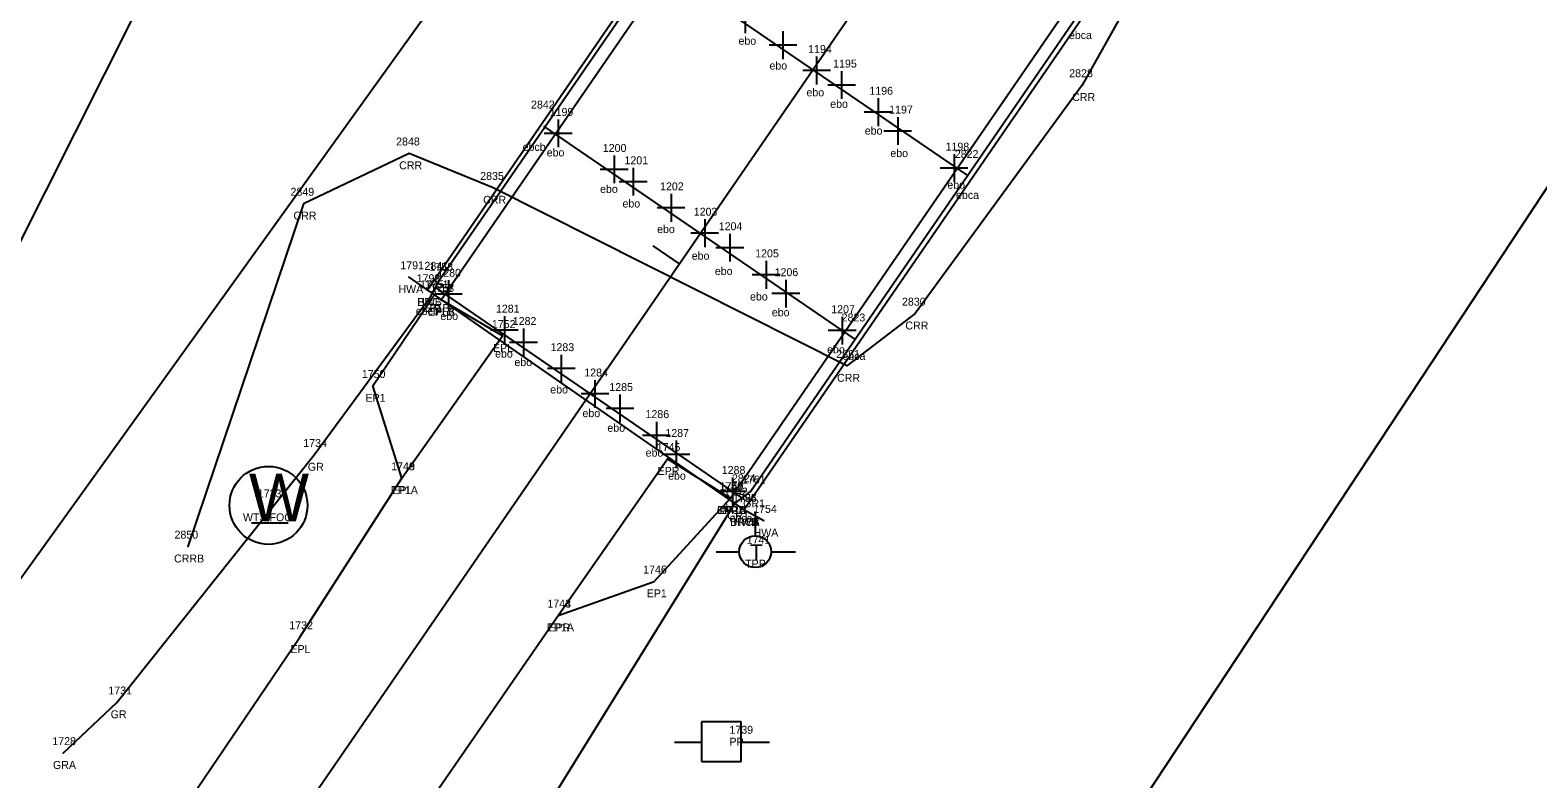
# Model space of a CAD drawing. Extents: x 2266664 to 2272542, y 716533 to 724777.
# Drawn here: x 2268915.8 to 2269105.7, y 719810.9 to 719905.2 of the extents above; entities that cross this region are included whole.
import ezdxf

# ---------------------------------------------------------------- set-up
doc = ezdxf.new("R2010")
doc.units = 0
for name, color, linetype in [('RD_EX_Bridge', 7, 'Continuous'), ('RD_EX_Bridge_txCode', 7, 'Continuous'), ('RD_EX_Conc', 7, 'Continuous'), ('RD_EX_Conc_txCode', 7, 'Continuous'), ('RD_EX_GuardRail', 7, 'Continuous'), ('RD_EX_GuardRail_txCode', 7, 'Continuous'), ('RD_EX_H2O', 7, 'Continuous'), ('RD_EX_H2O_txCode', 7, 'Continuous'), ('RD_EX_Misc', 7, 'Continuous'), ('RD_EX_Misc_txCode', 7, 'Continuous'), ('RD_EX_Road', 7, 'Continuous'), ('RD_EX_Road_txCode', 7, 'Continuous'), ('RD_EX_UT', 7, 'Continuous'), ('RD_EX_UT_txCode', 7, 'Continuous'), ('RD_EX_VEG', 7, 'Continuous'), ('RD_HC_Cl', 7, 'Continuous'), ('RD_HC_Data_Tic', 7, 'Continuous'), ('RD_SMD_Locator', 7, 'Continuous')]:
    doc.layers.add(name, color=color, linetype=linetype)

msp = doc.modelspace()

# ---------------------------------------------------------------- linework, layer by layer
at = {"layer": 'RD_EX_Bridge'}
for p, q in [((2268963.52, 719874.06), (2268965.85, 719872.44)), ((2269008.24, 719843.39), (2269005.71, 719844.75))]:
    msp.add_line(p, q, dxfattribs=at)
msp.add_lwpolyline([(2269005.71, 719844.75), (2269233.07, 720175.43), (2269193.18, 720202.86), (2268965.85, 719872.44), (2269005.71, 719844.75)], dxfattribs=at)
at = {"layer": 'RD_EX_Conc'}
for points in [[(2268967.59, 719871.21), (2269010.36, 719933.37), (2269052.74, 719994.95), (2269096, 720057.76), (2269138.05, 720118.85), (2269194.93, 720201.62)], [(2269004.04, 719846.24), (2269046.75, 719908.42), (2269089.1, 719970.17), (2269131.56, 720031.81), (2269174.47, 720094.11), (2269231.14, 720176.62)]]:
    msp.add_lwpolyline(points, dxfattribs=at)
at = {"layer": 'RD_EX_GuardRail'}
for points in [[(2268966.72, 719781.34), (2268981.11, 719807.65), (2269004.56, 719845.55), (2269006.56, 719847.08), (2269048.04, 719907.43), (2269090.37, 719969.18), (2269132.94, 720030.91), (2269175.81, 720093.43), (2269231.32, 720174.06), (2269253.93, 720204.36), (2269271.7, 720223.93)], [(2268919.97, 719814.14), (2268926.75, 719820.52), (2268951.58, 719851.69), (2268966.29, 719871.68), (2268967.47, 719873.87), (2269009.19, 719934.42), (2269051.44, 719995.68), (2269094.56, 720058.42), (2269136.79, 720119.9), (2269193.57, 720202.38)]]:
    msp.add_lwpolyline(points, dxfattribs=at)
at = {"layer": 'RD_EX_H2O'}
for points in [[(2269026.84, 720028.11), (2268972.74, 719968.59), (2268939.93, 719929), (2268910.32, 719870.19), (2268897.54, 719838.49), (2268888.45, 719839.47), (2268875.86, 719855.03)], [(2269107.58, 719973.56), (2269095.28, 719977.57), (2269070.98, 719938.72), (2269048.32, 719898.25), (2269027.3, 719869.48), (2269018.7, 719862.89), (2268974.14, 719885.31), (2268963.55, 719889.65), (2268950.25, 719883.32), (2268935.68, 719840.14)]]:
    msp.add_lwpolyline(points, dxfattribs=at)
at = {"layer": 'RD_EX_Misc'}
for p, q in [((2269033.91, 719886.87), (2268994.62, 719913.71)), ((2269005.87, 719908.31), (2269005.87, 719904.81)), ((2269010.63, 719905.03), (2269010.63, 719901.53)), ((2269012.38, 719903.28), (2269008.88, 719903.28)), ((2269014.87, 719901.84), (2269014.87, 719898.34)), ((2269016.62, 719900.09), (2269013.12, 719900.09)), ((2269018.02, 719900.01), (2269018.02, 719896.51)), ((2269019.77, 719898.26), (2269016.27, 719898.26)), ((2269022.61, 719896.59), (2269022.61, 719893.09)), ((2269024.36, 719894.84), (2269020.86, 719894.84)), ((2269019.66, 719866.29), (2268980.54, 719893.1)), ((2268982.32, 719893.92), (2268982.32, 719890.42)), ((2269025.09, 719894.22), (2269025.09, 719890.72)), ((2268984.07, 719892.17), (2268980.57, 719892.17)), ((2269026.84, 719892.47), (2269023.34, 719892.47)), ((2268989.38, 719889.39), (2268989.38, 719885.89)), ((2269032.19, 719889.56), (2269032.19, 719886.06)), ((2268991.13, 719887.64), (2268987.63, 719887.64)), ((2268991.78, 719887.83), (2268991.78, 719884.33)), ((2269033.94, 719887.81), (2269030.44, 719887.81)), ((2268993.53, 719886.08), (2268990.03, 719886.08)), ((2268996.54, 719884.55), (2268996.54, 719881.05)), ((2268998.29, 719882.8), (2268994.79, 719882.8)), ((2269000.79, 719881.36), (2269000.79, 719877.86)), ((2269002.54, 719879.61), (2268999.04, 719879.61)), ((2269003.94, 719879.53), (2269003.94, 719876.03)), ((2269005.69, 719877.78), (2269002.19, 719877.78)), ((2269008.52, 719876.11), (2269008.52, 719872.61)), ((2268968.5, 719873.67), (2268968.5, 719870.17)), ((2269010.27, 719874.36), (2269006.77, 719874.36)), ((2269011, 719873.74), (2269011, 719870.24)), ((2268970.25, 719871.92), (2268966.75, 719871.92)), ((2269005.84, 719846.04), (2268966.84, 719872.79)), ((2269012.75, 719871.99), (2269009.25, 719871.99)), ((2268975.55, 719869.15), (2268975.55, 719865.65)), ((2269018.1, 719869.08), (2269018.1, 719865.58)), ((2268977.3, 719867.4), (2268973.8, 719867.4)), ((2268977.96, 719867.59), (2268977.96, 719864.09)), ((2269019.85, 719867.33), (2269016.35, 719867.33)), ((2268979.71, 719865.84), (2268976.21, 719865.84)), ((2268982.72, 719864.3), (2268982.72, 719860.8)), ((2268984.47, 719862.55), (2268980.97, 719862.55)), ((2268986.96, 719861.11), (2268986.96, 719857.61)), ((2268988.71, 719859.36), (2268985.21, 719859.36)), ((2268990.11, 719859.28), (2268990.11, 719855.78)), ((2268991.86, 719857.53), (2268988.36, 719857.53)), ((2268994.7, 719855.87), (2268994.7, 719852.37)), ((2268996.45, 719854.12), (2268992.95, 719854.12)), ((2268997.18, 719853.5), (2268997.18, 719850)), ((2268998.93, 719851.75), (2268995.43, 719851.75)), ((2269006.03, 719847.08), (2269002.53, 719847.08)), ((2269004.28, 719848.83), (2269004.28, 719845.33))]:
    msp.add_line(p, q, dxfattribs=at)
at = {"layer": 'RD_EX_Road'}
for points in [[(2268844.96, 719677.11), (2268896.55, 719753.72), (2268929.83, 719802.76), (2268931.8, 719802.17), (2268949.81, 719828.73), (2268962.65, 719848.75), (2268975.33, 719866.66), (2268967.59, 719871.21)], [(2268962.65, 719848.75), (2268958.99, 719860.37), (2268966.63, 719871.67)], [(2268842.45, 719629.17), (2268908.71, 719725.27), (2268929.59, 719755.12), (2268982.31, 719831.46), (2268996.08, 719851.17), (2269004.04, 719846.24)], [(2268982.31, 719831.46), (2268994.4, 719835.75), (2269004.04, 719846.24)]]:
    msp.add_lwpolyline(points, dxfattribs=at)
at = {"layer": 'RD_EX_UT'}
for p, q in [((2269007.14, 719844.56), (2269007.14, 719841.49)), ((2268943.72, 719843.13), (2268948.34, 719843.13)), ((2269002.21, 719839.5), (2269005.14, 719839.5)), ((2269009.14, 719839.5), (2269012.21, 719839.5)), ((2269005.39, 719818.08), (2269000.39, 719818.08)), ((2269000.39, 719818.08), (2269000.39, 719813.08)), ((2269005.39, 719813.08), (2269005.39, 719818.08)), ((2268996.96, 719815.51), (2269000.43, 719815.51)), ((2269005.32, 719815.51), (2269008.96, 719815.51)), ((2269000.39, 719813.08), (2269005.39, 719813.08))]:
    msp.add_line(p, q, dxfattribs=at)
for centre, radius in [((2268945.84, 719845.33), 4.91), ((2269007.14, 719839.49), 2)]:
    msp.add_circle(centre, radius, dxfattribs=at)
at = {"layer": 'RD_EX_VEG'}
for points in [[(2268819.78, 719716.8), (2268871.54, 719776.21), (2269193.85, 720224.65), (2269408.57, 720538.5), (2269589.67, 720791.77), (2270047.56, 721479.8), (2270363.13, 721951.09), (2270746.65, 722498.38), (2270919.94, 722752.82), (2271017.26, 722923.37)], [(2268988.31, 719705.64), (2269316.7, 720203.55), (2269323.19, 720195.95)]]:
    msp.add_lwpolyline(points, dxfattribs=at)
at = {"layer": 'RD_HC_Cl'}
msp.add_line((2267342.91, 717471.2), (2272360.46, 724762.59), dxfattribs=at)
at = {"layer": 'RD_HC_Data_Tic'}
msp.add_line((2268997.6, 719875.76), (2268994.31, 719878.03), dxfattribs=at)
at = {"layer": 'RD_SMD_Locator'}
for centre in [(2269048.32, 719898.25), (2268963.55, 719889.65), (2268974.14, 719885.31), (2268950.25, 719883.32), (2268963.52, 719874.06), (2268967.47, 719873.87), (2268965.85, 719872.44), (2268965.85, 719872.44), (2268966.29, 719871.68), (2268966.63, 719871.67), (2268967.59, 719871.21), (2268967.59, 719871.21), (2269027.3, 719869.48), (2268975.33, 719866.66), (2269018.7, 719862.89), (2268958.99, 719860.37), (2268951.58, 719851.69), (2268996.08, 719851.17), (2268962.65, 719848.75), (2268962.65, 719848.75), (2269006.56, 719847.08), (2269004.04, 719846.24), (2269004.04, 719846.24), (2269004.04, 719846.24), (2269004.56, 719845.55), (2269005.71, 719844.75), (2269005.71, 719844.75), (2269005.71, 719844.75), (2269008.24, 719843.39), (2268935.68, 719840.14), (2268994.4, 719835.75), (2268982.31, 719831.46), (2268982.31, 719831.46), (2268949.81, 719828.73), (2268926.75, 719820.52), (2268919.97, 719814.14)]:
    msp.add_circle(centre, 0.001, dxfattribs=at)

# ---------------------------------------------------------------- texts
at = {"layer": 'RD_EX_Bridge_txCode'}
for s, p in [('1791', (2268962.45, 719875.06)), ('1792', (2268964.51, 719873.44)), ('1793', (2268964.51, 719873.44)), ('HWA', (2268962.21, 719872.06)), ('HWB', (2268964.56, 719870.44)), ('BRC', (2268964.6, 719870.44)), ('1756', (2269004.34, 719845.75)), ('1794', (2269004.36, 719845.75)), ('1755', (2269004.36, 719845.75)), ('1754', (2269006.89, 719844.39)), ('BRCA', (2269003.97, 719842.75)), ('BRCB', (2269003.98, 719842.75)), ('HWB', (2269004.42, 719842.75)), ('HWA', (2269006.93, 719841.39))]:
    msp.add_text(s, height=1, dxfattribs=at).set_placement(p)
at = {"layer": 'RD_EX_Conc_txCode'}
for s, p in [('1757', (2268966.24, 719872.21)), ('CFLA', (2268965.89, 719869.21)), ('1759', (2269002.69, 719847.24)), ('CFRA', (2269002.32, 719844.24))]:
    msp.add_text(s, height=1, dxfattribs=at).set_placement(p)
at = {"layer": 'RD_EX_GuardRail_txCode'}
for s, p in [('1758', (2268966.12, 719874.87)), ('1735', (2268964.94, 719872.68)), ('GR', (2268966.69, 719871.87)), ('GR', (2268965.51, 719869.68)), ('1734', (2268950.23, 719852.69)), ('GR', (2268950.8, 719849.69)), ('1761', (2269005.48, 719848.08)), ('1742', (2269003.22, 719846.55)), ('GR1', (2269005.62, 719845.08)), ('GR1', (2269003.62, 719843.55)), ('1731', (2268925.68, 719821.52)), ('GR', (2268925.97, 719818.52)), ('1728', (2268918.62, 719815.14)), ('GRA', (2268918.7, 719812.14))]:
    msp.add_text(s, height=1, dxfattribs=at).set_placement(p)
at = {"layer": 'RD_EX_H2O_txCode'}
for s, p in [('2828', (2269046.69, 719899.25)), ('CRR', (2269047.06, 719896.25)), ('2848', (2268961.92, 719890.65)), ('CRR', (2268962.3, 719887.65)), ('2835', (2268972.51, 719886.31)), ('2849', (2268948.62, 719884.32)), ('CRR', (2268972.88, 719883.31)), ('CRR', (2268948.99, 719881.32)), ('2830', (2269025.63, 719870.48)), ('CRR', (2269026.05, 719867.48)), ('2831', (2269017.35, 719863.89)), ('CRR', (2269017.45, 719860.89)), ('2850', (2268934.01, 719841.14)), ('CRRB', (2268933.95, 719838.14))]:
    msp.add_text(s, height=1, dxfattribs=at).set_placement(p)
at = {"layer": 'RD_EX_Misc_txCode'}
for s, p in [('ebo', (2269005.04, 719903.34)), ('ebca', (2269046.65, 719904.05)), ('1194', (2269013.81, 719902.29)), ('ebo', (2269008.94, 719900.21)), ('1195', (2269016.96, 719900.46)), ('ebo', (2269013.6, 719896.84)), ('ebo', (2269016.59, 719895.39)), ('1196', (2269021.52, 719897.04)), ('2842', (2268978.91, 719895.3)), ('1199', (2268981.26, 719894.37)), ('1197', (2269024.02, 719894.67)), ('ebo', (2269020.94, 719892.02)), ('ebcb', (2268977.85, 719889.97)), ('1200', (2268987.95, 719889.84)), ('1198', (2269031.12, 719890.01)), ('ebo', (2268980.88, 719889.27)), ('1201', (2268990.68, 719888.28)), ('ebo', (2269024.16, 719889.19)), ('2822', (2269032.28, 719889.07)), ('ebo', (2268987.6, 719884.67)), ('1202', (2268995.16, 719885)), ('ebo', (2269031.34, 719885.21)), ('ebo', (2268990.43, 719882.84)), ('ebca', (2269032.43, 719883.92)), ('1203', (2268999.4, 719881.81)), ('ebo', (2268994.79, 719879.62)), ('1204', (2269002.55, 719879.98)), ('1205', (2269007.14, 719876.56)), ('2841', (2268965.49, 719874.99)), ('ebo', (2268999.15, 719876.26)), ('1280', (2268967.11, 719874.12)), ('ebo', (2269002.06, 719874.34)), ('1206', (2269009.59, 719874.19)), ('ebo', (2269006.49, 719871.13)), ('ebcb', (2268964.39, 719869.31)), ('1281', (2268974.49, 719869.6)), ('ebo', (2269009.24, 719869.14)), ('1207', (2269016.72, 719869.53)), ('ebo', (2268967.49, 719868.68)), ('1282', (2268976.61, 719868.04)), ('2823', (2269018.03, 719868.49)), ('ebo', (2268974.38, 719863.94)), ('1283', (2268981.37, 719864.75)), ('ebo', (2269016.2, 719864.47)), ('ebca', (2269018.13, 719863.65)), ('ebo', (2268976.82, 719862.87)), ('1284', (2268985.62, 719861.56)), ('ebo', (2268981.33, 719859.42)), ('1285', (2268988.77, 719859.73)), ('ebo', (2268985.39, 719856.44)), ('1286', (2268993.33, 719856.32)), ('ebo', (2268988.52, 719854.6)), ('1287', (2268995.83, 719853.95)), ('ebo', (2268993.34, 719851.47)), ('ebo', (2268996.17, 719848.56)), ('1288', (2269002.93, 719849.28)), ('2824', (2269004.21, 719848.24)), ('ebo', (2269002.67, 719844.5)), ('ebca', (2269003.9, 719843.22))]:
    msp.add_text(s, height=1, dxfattribs=at).set_placement(p)
at = {"layer": 'RD_EX_Road_txCode'}
for s, p in [('1751', (2268965.57, 719872.67)), ('1753', (2268966.24, 719872.21)), ('EP1B', (2268965.24, 719869.67)), ('EPLB', (2268965.91, 719869.21)), ('1752', (2268973.98, 719867.66)), ('EPL', (2268974.12, 719864.66)), ('1750', (2268957.6, 719861.37)), ('EP1', (2268958.06, 719858.37)), ('1745', (2268994.74, 719852.17)), ('1748', (2268961.3, 719849.75)), ('1749', (2268961.3, 719849.75)), ('EPR', (2268994.85, 719849.17)), ('EP1A', (2268961.24, 719846.75)), ('EPL', (2268961.44, 719846.75)), ('1760', (2269002.63, 719847.24)), ('1747', (2269002.69, 719847.24)), ('EPRB', (2269002.33, 719844.24)), ('EP1B', (2269002.64, 719844.24)), ('1746', (2268993.03, 719836.75)), ('EP1', (2268993.48, 719833.75)), ('1743', (2268980.97, 719832.46)), ('1744', (2268980.97, 719832.46)), ('1732', (2268948.47, 719829.73)), ('EP1A', (2268980.9, 719829.46)), ('EPR', (2268981.09, 719829.46)), ('EPL', (2268948.61, 719826.73))]:
    msp.add_text(s, height=1, dxfattribs=at).set_placement(p)
at = {"layer": 'RD_EX_UT'}
for s, height, p in [('W', 6, (2268943.38, 719843.33)), ('T', 2, (2269006.47, 719838.44))]:
    msp.add_text(s, height=height, dxfattribs=at).set_placement(p)
at = {"layer": 'RD_EX_UT_txCode'}
for s, p in [('1733', (2268944.5, 719846.33)), ('WTS FOC', (2268942.63, 719843.33)), ('1741', (2269006.07, 719840.49)), ('TPP', (2269005.87, 719837.49)), ('1739', (2269003.9, 719816.57)), ('PP', (2269003.9, 719815.07))]:
    msp.add_text(s, height=1, dxfattribs=at).set_placement(p)

doc.saveas('drawing.dxf')
